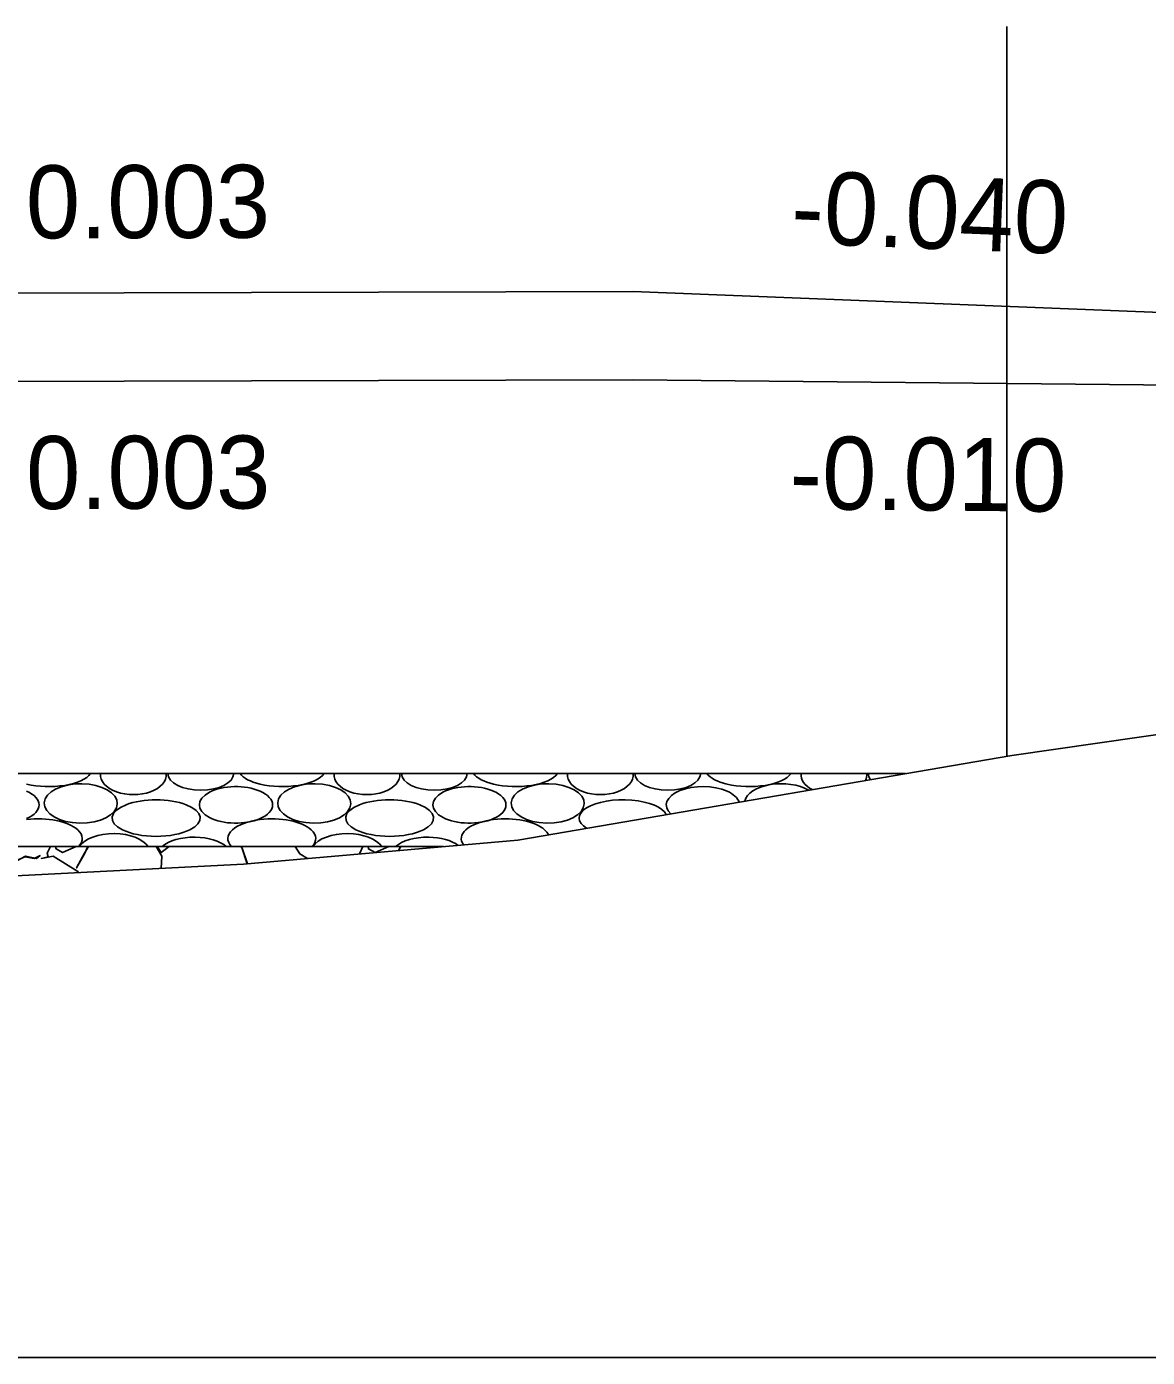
# Model space of a CAD drawing. Extents: x -26 to 4781, y -31 to 24738.
# Drawn here: x 2303.69 to 2319.04, y 14500 to 14518.24 of the extents above; entities that cross this region are included whole.
import ezdxf

# ---------------------------------------------------------------- set-up
doc = ezdxf.new("R2010")
doc.units = 0
for name, color, linetype in [('DESIGN - SHEET - Light Grid', 7, 'Continuous'), ('DESIGN - TRANSPORTATION - Proposed Layout Patterning', 7, 'Continuous'), ('DESIGN - TYPICAL - Finished Grade and Subgrade', 7, 'Continuous'), ('DESIGN - TYPICAL - Finished Grade Slopes Text', 7, 'Continuous'), ('DESIGN - TYPICAL - Subgrade Cross Slope Text', 7, 'Continuous'), ('GEOTECHNICAL – SCRATCH – Level 1', 7, 'Continuous'), ('SURVEY - GROUND - Top of Ground', 7, 'Continuous'), ('SURVEY - PROPERTY - ROW Lines', 7, 'Continuous')]:
    doc.layers.add(name, color=color, linetype=linetype)

msp = doc.modelspace()

# ---------------------------------------------------------------- linework, layer by layer
at = {"layer": 'DESIGN - SHEET - Light Grid'}
msp.add_line((2300, 14500), (2600, 14500), dxfattribs=at)
at = {"layer": 'DESIGN - TRANSPORTATION - Proposed Layout Patterning'}
for p, q in [((2306.71, 14506.764), (2306.633, 14507)), ((2308.813, 14507), (2308.782, 14506.946)), ((2308.782, 14506.946), (2308.808, 14507))]:
    msp.add_line(p, q, dxfattribs=at)
for points in [[(2304.395, 14506.644), (2304.391, 14506.659), (2304.051, 14506.869), (2303.891, 14506.839), (2303.981, 14506.859), (2303.971, 14506.909), (2304.016, 14507)], [(2304.085, 14507), (2304.091, 14506.969), (2304.181, 14506.919), (2304.368, 14507)], [(2304.533, 14507), (2304.481, 14506.909), (2304.371, 14506.709), (2304.481, 14506.899), (2304.528, 14507)], [(2305.464, 14507), (2305.541, 14506.869), (2305.532, 14506.702)], [(2305.64, 14507), (2305.531, 14506.919), (2305.475, 14507)], [(2306.623, 14507), (2306.641, 14506.979), (2306.714, 14506.765)], [(2307.367, 14507), (2307.431, 14506.899), (2307.535, 14506.837)], [(2308.252, 14506.9), (2308.251, 14506.909), (2308.296, 14507)], [(2308.365, 14507), (2308.371, 14506.969), (2308.461, 14506.919), (2308.648, 14507)], [(2303.466, 14506.597), (2303.481, 14506.779), (2303.661, 14506.859), (2303.791, 14506.839), (2303.871, 14506.879), (2303.821, 14506.839), (2303.671, 14506.869), (2303.501, 14506.779), (2303.421, 14506.749), (2303.442, 14506.595)]]:
    msp.add_lwpolyline(points, dxfattribs=at)
for centre, major_axis, ratio, start_param, end_param in [((2303.988, 14508.073), (-0.602, 0), 0.416667, 1.047185, 2.846662), ((2304.429, 14507.592), (-0.501, 0), 0.54, 1.545388, 7.825415), ((2305.151, 14507.983), (-0.451, 0), 0.6, 6.21895, 9.489014), ((2306.074, 14508.003), (-0.451, 0), 0.511111, 0.011602, 3.129991), ((2306.555, 14507.572), (-0.501, 0), 0.5, 3.991263, 8.575372), ((2307.187, 14508.073), (-0.602, 0), 0.416667, 0.29493, 1.047185), ((2307.187, 14508.073), (-0.602, 0), 0.416667, 1.047185, 2.846662), ((2307.628, 14507.592), (-0.501, 0), 0.54, 1.545388, 7.825415), ((2308.35, 14507.983), (-0.451, 0), 0.6, 6.21895, 9.489014), ((2309.273, 14508.003), (-0.451, 0), 0.511111, 0.011602, 3.129991), ((2309.754, 14507.572), (-0.501, 0), 0.5, 3.991263, 8.575372), ((2310.386, 14508.073), (-0.602, 0), 0.416667, 0.29493, 1.047185), ((2310.386, 14508.073), (-0.602, 0), 0.416667, 1.047185, 2.846662), ((2310.827, 14507.592), (-0.501, 0), 0.54, 1.545388, 7.825415), ((2311.549, 14507.983), (-0.451, 0), 0.6, 6.21895, 9.489014), ((2312.472, 14508.003), (-0.451, 0), 0.511111, 0.011602, 3.129991), ((2312.953, 14507.572), (-0.501, 0), 0.5, 3.991263, 6.793817), ((2313.584, 14508.073), (-0.602, 0), 0.416667, 0.29493, 1.047185), ((2313.585, 14508.073), (-0.602, 0), 0.416667, 1.047185, 2.846662), ((2314.026, 14507.592), (-0.501, 0), 0.54, 3.871375, 6.168233), ((2314.748, 14507.983), (-0.451, 0), 0.6, 6.21895, 7.126896), ((2314.748, 14507.983), (-0.451, 0), 0.6, 2.854514, 3.205828), ((2315.67, 14508.003), (-0.451, 0), 0.511111, 0.011602, 0.376077), ((2303.357, 14507.572), (-0.501, 0), 0.5, 2.292187, 3.991263), ((2305.462, 14507.391), (-0.602, 0), 0.416667, 2.446, 6.978671), ((2306.556, 14507.572), (-0.501, 0), 0.5, 2.292187, 3.991263), ((2308.661, 14507.391), (-0.602, 0), 0.416667, 2.446, 6.978671), ((2309.754, 14507.572), (-0.501, 0), 0.5, 2.292187, 3.991263), ((2312.953, 14507.572), (-0.501, 0), 0.5, 3.291901, 3.991263), ((2311.86, 14507.391), (-0.602, 0), 0.416667, 3.329825, 6.875636), ((2303.848, 14507.11), (-0.602, 0), 0.45, 3.602876, 4.982641), ((2307.046, 14507.11), (-0.602, 0), 0.45, 4.982641, 5.821976), ((2307.047, 14507.11), (-0.602, 0), 0.45, 3.602876, 4.982641), ((2310.245, 14507.11), (-0.602, 0), 0.45, 4.982641, 5.821976), ((2310.246, 14507.11), (-0.602, 0), 0.45, 3.602876, 4.982641), ((2303.848, 14507.11), (-0.602, 0), 0.45, 2.723371, 3.602877), ((2304.881, 14506.909), (-0.501, 0), 0.54, 4.698848, 5.942), ((2304.881, 14506.909), (-0.501, 0), 0.54, 3.482778, 4.691622), ((2305.462, 14507.391), (-0.602, 0), 0.416667, 0.695486, 2.446), ((2305.984, 14506.879), (-0.501, 0), 0.5, 4.691313, 5.780965), ((2305.984, 14506.879), (-0.501, 0), 0.5, 3.643813, 4.683059), ((2307.046, 14507.11), (-0.602, 0), 0.45, 5.821976, 6.701407), ((2307.047, 14507.11), (-0.602, 0), 0.45, 2.723371, 3.602877), ((2308.08, 14506.909), (-0.501, 0), 0.54, 4.698848, 5.942), ((2308.08, 14506.909), (-0.501, 0), 0.54, 3.482778, 4.691622), ((2308.661, 14507.391), (-0.602, 0), 0.416667, 0.695486, 2.446), ((2309.182, 14506.879), (-0.501, 0), 0.5, 4.691313, 5.780965), ((2309.182, 14506.879), (-0.501, 0), 0.5, 3.726066, 4.683059), ((2310.245, 14507.11), (-0.602, 0), 0.45, 5.821976, 6.605713), ((2310.246, 14507.11), (-0.602, 0), 0.45, 3.33203, 3.602877)]:
    msp.add_ellipse(centre, major_axis=major_axis, ratio=ratio, start_param=start_param, end_param=end_param, dxfattribs=at)
at = {"layer": 'DESIGN - TYPICAL - Finished Grade and Subgrade'}
for p, q in [((2302, 14514.582), (2312, 14514.607)), ((2312, 14514.607), (2322, 14514.207)), ((2302, 14513.372), (2312, 14513.397)), ((2312, 14513.397), (2322, 14513.297))]:
    msp.add_line(p, q, dxfattribs=at)
at = {"layer": 'GEOTECHNICAL – SCRATCH – Level 1'}
for p, q in [((2256.747, 14508), (2315.729, 14508)), ((2253.747, 14507), (2309.399, 14507))]:
    msp.add_line(p, q, dxfattribs=at)
at = {"layer": 'SURVEY - GROUND - Top of Ground'}
msp.add_lwpolyline([(2240.18, 14503.958), (2250.843, 14504.763), (2255.374, 14504.984), (2259.845, 14505.115), (2264.597, 14505.101), (2268.614, 14505.126), (2278.725, 14505.205), (2281.994, 14505.266), (2290, 14505.333), (2290.47, 14505.374), (2300, 14506.289), (2302.911, 14506.568), (2306.66, 14506.76), (2310.416, 14507.089), (2317.187, 14508.25), (2321.277, 14508.836)], dxfattribs=at)
at = {"layer": 'SURVEY - PROPERTY - ROW Lines'}
msp.add_line((2317.117, 14508.238), (2317.117, 14518.238), dxfattribs=at)

# ---------------------------------------------------------------- texts
at = {"layer": 'DESIGN - TYPICAL - Finished Grade Slopes Text'}
for s, rotation, p in [('0.003', 0.1465, (2303.678, 14515.336)), ('-0.040', 357.7094, (2314.149, 14515.271))]:
    msp.add_text(s, height=1, rotation=rotation, dxfattribs=at).set_placement(p)
at = {"layer": 'DESIGN - TYPICAL - Subgrade Cross Slope Text'}
for s, rotation, p in [('0.003', 0.1465, (2303.681, 14511.626)), ('-0.010', 359.4271, (2314.137, 14511.626))]:
    msp.add_text(s, height=1, rotation=rotation, dxfattribs=at).set_placement(p)

doc.saveas('drawing.dxf')
